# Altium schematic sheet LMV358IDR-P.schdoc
size 127 x 101 mm
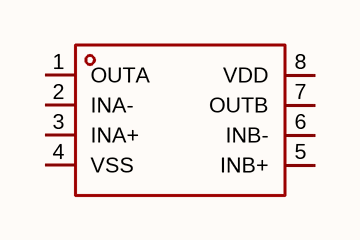
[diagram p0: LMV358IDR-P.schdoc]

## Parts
U?  lmv358idr_c2928703  [SOP-8_L4.9-W3.9-P1.27-LS6.0-BL]  (value not drawn)

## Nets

Not connected (* = marked no-connect by the designer): U? 1(OUTA) 2(INA-) 3(INA+) 4(VSS) 5(INB+) 6(INB-) 7(OUTB) 8(VDD)

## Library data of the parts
U? = lmv358idr_c2928703: 放大器数:2;轨到轨:轨到轨输入,轨到轨输出;增益带宽积(GBW):1MHz;输入失调电压(Vos):5mV;压摆率(SR):600V/ms;输入偏置电流(Ib):10pA;; Manufacturer: TECH PUBLIC(台舟); Symbol: LMV358IDR-P; AddInBom: yes; ModelId: 75c24a7891ee4dd6bdac16a7163ff87e; ModelName: SOP-8_L4.9-W3.9-P1.27-LS6.0-BL-1; ModelTransform: 192.913,236.22,0,0,0,0,-0.393,2.749,0; Number of Channels: 2; Maximum Power Supply Range (Vdd-Vss): 5.5V; Gain Bandwidth Product: 1MHz; Vos - Input Offset Voltage: 5mV; Input Offset Voltage Drift(Vos TC): 2uV/℃; Ib - Input Bias Current: 10pA; Input Voltage Noise Density: 20nV/√Hz@10kHz; Common Mode Rejection Ratio(CMRR): 65dB; Quiescent Current: 40uA; Output Current: 20mA; Single supply: 2.5V~5.5V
